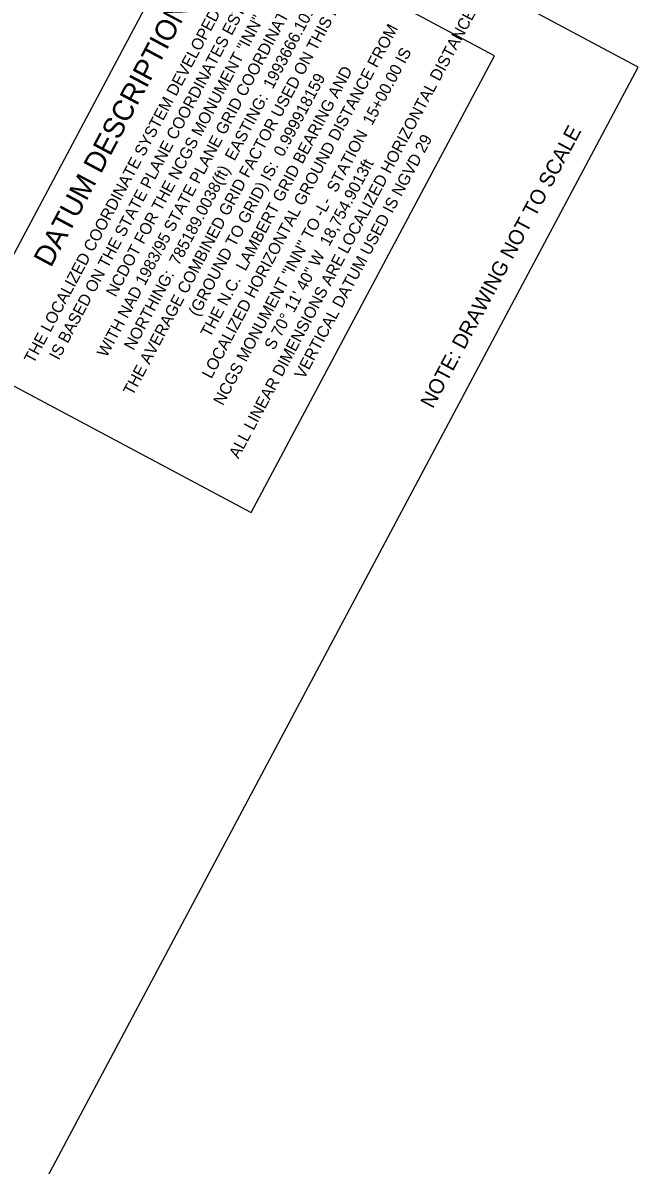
# Model space of a CAD drawing. Extents: x 1979034 to 1987549, y 771535 to 781988.
# Drawn here: x 1985403 to 1987549, y 775446 to 779426 of the extents above; entities that cross this region are included whole.
import ezdxf

# ---------------------------------------------------------------- set-up
doc = ezdxf.new("R2010")
doc.units = 0
for name, color, linetype in [('CTL Sheet Border CELL', 7, 'Continuous'), ('Old_Level_2', 7, 'Continuous'), ('Sheet Data Field CELL', 7, 'Continuous')]:
    doc.layers.add(name, color=color, linetype=linetype)

msp = doc.modelspace()

# ---------------------------------------------------------------- linework, layer by layer
at = {"layer": 'CTL Sheet Border CELL'}
msp.add_lwpolyline([(1982714.7, 781848.1), (1979034.2, 774941.4), (1983868.8, 772365.1), (1987549.3, 779271.7)], close=True, dxfattribs=at)
at = {"layer": 'Old_Level_2'}
msp.add_lwpolyline([(1986199.1, 777719.5), (1987047.7, 779311.9), (1986028.5, 779855), (1985179.9, 778262.6)], close=True, dxfattribs=at)

# ---------------------------------------------------------------- texts
for s, height, p in [('THE LOCALIZED COORDINATE SYSTEM DEVELOPED FOR THIS PROJECT', 40.6, (1985441, 778236.1)), ('IS BASED ON THE STATE PLANE COORDINATES ESTABLISHED BY', 40.6, (1985528.4, 778248.2)), ('THE AVERAGE COMBINED GRID FACTOR USED ON THIS PROJECT', 40.6, (1985786.3, 778124.3)), ('WITH NAD 1983/95 STATE PLANE GRID COORDINATES OF', 40.6, (1985695.4, 778257.8)), ('NORTHING:  785189.0038(ft)  EASTING:  1993666.1012(ft)', 40.6, (1985789.4, 778282.2)), ('DATUM DESCRIPTION', 72.178, (1985500.9, 778570.8)), ('ALL LINEAR DIMENSIONS ARE LOCALIZED HORIZONTAL DISTANCES', 40.6, (1986155.2, 777904.9)), ('NCDOT FOR THE NCGS MONUMENT "INN"', 40.6, (1985726.7, 778468.4)), ('LOCALIZED HORIZONTAL GROUND DISTANCE FROM', 40.6, (1986060.7, 778183.5)), ('NCGS MONUMENT "INN" TO -L-  STATION  15+00.00 IS', 40.6, (1986101, 778090)), ('THE N.C.  LAMBERT GRID BEARING AND', 40.6, (1986056.3, 778327.1)), ('(GROUND TO GRID) IS:  0.999918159', 40.6, (1986014.3, 778400.3)), ('VERTICAL DATUM USED IS NGVD 29', 40.6, (1986383.8, 778182)), ('S 70%%d 11\' 40" W  18,754.9013ft', 40.6, (1986278.8, 778282.7))]:
    msp.add_text(s, height=height, rotation=61.9471, dxfattribs=at).set_placement(p)
at = {"layer": 'Sheet Data Field CELL'}
msp.add_text('NOTE: DRAWING NOT TO SCALE', height=52.174, rotation=61.8418, dxfattribs=at).set_placement((1986833, 778079.5))

doc.saveas('drawing.dxf')
